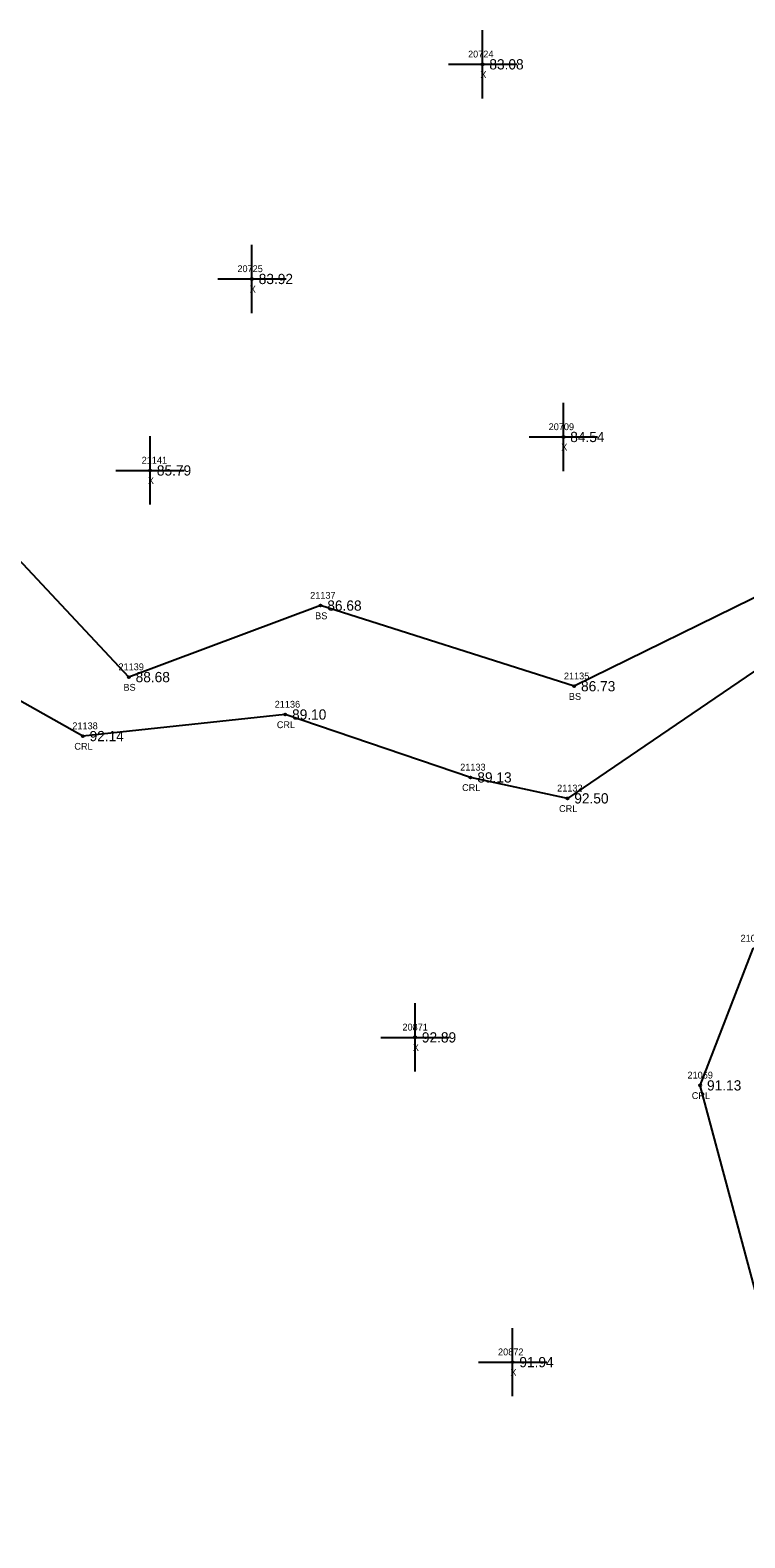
# Model space of a CAD drawing. Extents: x 2530197 to 2532051, y 935230 to 936631.
# Drawn here: x 2530944.6 to 2531049.2, y 935952.3 to 936173.1 of the extents above; entities that cross this region are included whole.
import ezdxf

# ---------------------------------------------------------------- set-up
doc = ezdxf.new("R2010")
doc.units = 0
for name, color, linetype in [('RD_DTM_BkLn2', 7, 'Continuous'), ('RD_DTM_BkLn_txCode', 7, 'Continuous'), ('RD_EX_H2O', 7, 'Continuous'), ('RD_EX_H2O_txCode', 7, 'Continuous'), ('RD_EX_Misc', 7, 'Continuous'), ('RD_EX_Misc_txCode', 7, 'Continuous'), ('RD_EX_TX_H2O_ELEV', 7, 'Continuous'), ('RD_EX_TX_Misc_ELEV', 7, 'Continuous'), ('RD_SMD_Locator', 7, 'Continuous')]:
    doc.layers.add(name, color=color, linetype=linetype)

msp = doc.modelspace()

# ---------------------------------------------------------------- linework, layer by layer
at = {"layer": 'RD_DTM_BkLn2'}
msp.add_lwpolyline([(2531052.84, 936091.07), (2531024.22, 936076.99), (2530987.08, 936088.8), (2530959.02, 936078.33), (2530937.87, 936100.94), (2530909.67, 936126.05), (2530891.79, 936131.19), (2530874.19, 936136.38), (2530849.99, 936134.78), (2530837.59, 936141.92), (2530795.33, 936166.72)], dxfattribs=at)
at = {"layer": 'RD_EX_H2O'}
msp.add_lwpolyline([(2531078.88, 935952.28), (2531078.88, 935952.28), (2531082.9, 935955.37), (2531071.89, 935962.43), (2531052.52, 935981.82), (2531042.66, 936018.54), (2531050.4, 936038.59), (2531079.35, 936050.48), (2531076.46, 936052.29), (2531062.77, 936059.41), (2531060.27, 936060.12), (2531061.98, 936077.76), (2531053.99, 936081.48), (2531023.23, 936060.57), (2531009.04, 936063.64), (2530981.92, 936072.85), (2530952.28, 936069.69), (2530922.53, 936086.42), (2530896.36, 936118.01), (2530886.54, 936120.09), (2530870.44, 936126.5), (2530844.88, 936119.11), (2530827.4, 936131.93), (2530794.88, 936161.74)], dxfattribs=at)
at = {"layer": 'RD_EX_Misc'}
for p, q in [((2531010.8, 936163.06), (2531010.8, 936173.06)), ((2531005.8, 936168.06), (2531015.8, 936168.06)), ((2530977.04, 936131.63), (2530977.04, 936141.63)), ((2530972.04, 936136.63), (2530982.04, 936136.63)), ((2531022.64, 936108.49), (2531022.64, 936118.49)), ((2530962.13, 936103.59), (2530962.13, 936113.59)), ((2531017.64, 936113.49), (2531027.64, 936113.49)), ((2530957.13, 936108.59), (2530967.13, 936108.59)), ((2531000.92, 936020.57), (2531000.92, 936030.57)), ((2530995.92, 936025.57), (2531005.92, 936025.57)), ((2531015.19, 935973.01), (2531015.19, 935983.01)), ((2531010.19, 935978.01), (2531020.19, 935978.01))]:
    msp.add_line(p, q, dxfattribs=at)
at = {"layer": 'RD_SMD_Locator'}
for centre in [(2531010.8, 936168.06), (2530977.04, 936136.63), (2531022.64, 936113.49), (2530962.13, 936108.59), (2530987.08, 936088.8), (2530959.02, 936078.33), (2531024.22, 936076.99), (2530981.92, 936072.85), (2530952.28, 936069.69), (2531009.04, 936063.64), (2531023.23, 936060.57), (2531000.92, 936025.57), (2531042.66, 936018.54), (2531015.19, 935978.01)]:
    msp.add_circle(centre, 0.15, dxfattribs=at)

# ---------------------------------------------------------------- texts
at = {"layer": 'RD_DTM_BkLn_txCode'}
for s, p in [('21137', (2530985.57, 936089.8)), ('BS', (2530986.3, 936086.8)), ('21139', (2530957.51, 936079.33)), ('21135', (2531022.71, 936077.99)), ('BS', (2530958.24, 936076.33)), ('BS', (2531023.44, 936074.99))]:
    msp.add_text(s, height=1, dxfattribs=at).set_placement(p)
at = {"layer": 'RD_EX_H2O_txCode'}
for s, p in [('21136', (2530980.38, 936073.85)), ('21138', (2530950.76, 936070.69)), ('CRL', (2530980.69, 936070.85)), ('CRL', (2530951.05, 936067.69)), ('21133', (2531007.53, 936064.64)), ('CRL', (2531007.81, 936061.64)), ('21132', (2531021.72, 936061.57)), ('CRL', (2531022, 936058.57)), ('21072', (2531048.57, 936039.59)), ('21069', (2531040.8, 936019.54)), ('CRL', (2531041.43, 936016.54))]:
    msp.add_text(s, height=1, dxfattribs=at).set_placement(p)
at = {"layer": 'RD_EX_Misc_txCode'}
for s, p in [('20724', (2531008.68, 936169.06)), ('X', (2531010.48, 936166.06)), ('20725', (2530974.92, 936137.63)), ('X', (2530976.72, 936134.63)), ('20709', (2531020.48, 936114.49)), ('X', (2531022.32, 936111.49)), ('21141', (2530960.91, 936109.59)), ('X', (2530961.82, 936106.59)), ('20871', (2530999.08, 936026.57)), ('X', (2531000.6, 936023.57)), ('20872', (2531013.07, 935979.01)), ('X', (2531014.88, 935976.01))]:
    msp.add_text(s, height=1, dxfattribs=at).set_placement(p)
at = {"layer": 'RD_EX_TX_H2O_ELEV'}
for s, p in [('89.10', (2530982.92, 936072.1)), ('92.14', (2530953.28, 936068.94)), ('89.13', (2531010.04, 936062.89)), ('92.50', (2531024.23, 936059.82)), ('91.13', (2531043.66, 936017.79))]:
    msp.add_text(s, height=1.5, dxfattribs=at).set_placement(p)
at = {"layer": 'RD_EX_TX_Misc_ELEV'}
for s, p in [('83.08', (2531011.8, 936167.31)), ('83.92', (2530978.04, 936135.88)), ('84.54', (2531023.64, 936112.74)), ('85.79', (2530963.13, 936107.84)), ('86.68', (2530988.08, 936088.05)), ('88.68', (2530960.02, 936077.58)), ('86.73', (2531025.22, 936076.24)), ('92.89', (2531001.92, 936024.82)), ('91.94', (2531016.19, 935977.26))]:
    msp.add_text(s, height=1.5, dxfattribs=at).set_placement(p)

doc.saveas('drawing.dxf')
